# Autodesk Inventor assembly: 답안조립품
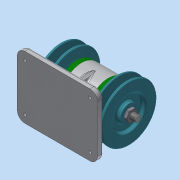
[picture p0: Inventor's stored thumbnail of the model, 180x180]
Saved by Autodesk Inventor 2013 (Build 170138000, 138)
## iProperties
Created: 2019-09
Part Number: 답안조립품
Document SubType Name: Assembly
Designer: Administrator
Author: Administrator
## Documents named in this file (10)
- C:\Users\Administrator\Desktop\새 폴더\답안조립품.iam
- C:\Users\Administrator\Desktop\새 폴더\본체.ipt
- C:\Users\Administrator\Desktop\새 폴더\V-벨트풀리.ipt
- C:\Users\Administrator\Desktop\새 폴더\너트 M10x1.ipt
- C:\Users\Administrator\Desktop\새 폴더\베어링 6004.ipt
- C:\Users\Administrator\Desktop\새 폴더\볼트 M4.ipt
- C:\Users\Administrator\Desktop\새 폴더\오일 실 17 30 5.ipt
- C:\Users\Administrator\Desktop\새 폴더\축.ipt
- C:\Users\Administrator\Desktop\새 폴더\커버.ipt
- C:\Users\Administrator\Desktop\새 폴더\키 5 x 5 x 12.ipt
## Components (2 placed, 1 different names)
1. V-벨트풀리:1
2. V-벨트풀리:2
